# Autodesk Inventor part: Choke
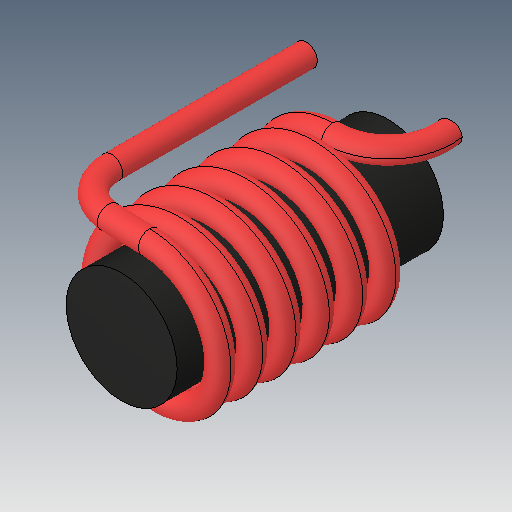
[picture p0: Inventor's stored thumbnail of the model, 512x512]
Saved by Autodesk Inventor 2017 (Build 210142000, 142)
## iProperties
Created: 2005-12
Part Number: Choke
Material: Generic
Document SubType Name: Modeling
Designer: DanielSeverino
Density: 1 g/cm^3
Appearance: Default
Author: DanielSeverino
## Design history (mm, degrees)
feature "Solid1"
feature "Solid1:1"
body "Solid2"
body "Solid3"
